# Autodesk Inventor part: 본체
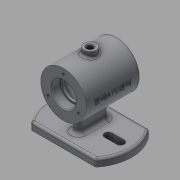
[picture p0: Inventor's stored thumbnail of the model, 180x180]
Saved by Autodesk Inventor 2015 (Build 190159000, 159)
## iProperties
Created: 2017-12
Part Number: 본체
Material: 일반
Document SubType Name: Modeling
Designer: SCD-A03
Density: 1 g/cm^3
Appearance: 기본값
Author: SCD-A03
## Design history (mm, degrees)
sketch "스케치1"
  geometry: L1 (-55, 0)-(55, 0); L2 (-42.426, 35)-(42.426, 35); L3 (-42.426, -35)-(42.426, -35); A1 r 55 centre (0, 0) between (-42.426, 35) and (-42.426, -35); A2 r 55 centre (0, 0) between (42.426, -35) and (42.426, 35); 1 further point
  constraints: 6 end point, 6 point on circle, 2 centre point, 2 parallel, 1 coincident, 1 horizontal
  dimensions: "d1" = 35 distance between parallel lines of L3 L1; "d2" = 35 distance between parallel lines of L2 L1
extrude "돌출1" new body sketch "스케치1" distance "d3" = 10; taper "d4" = 0 deg
sketch "스케치2"
  geometry: L1 (0, -15)-(0, 15); L2 (5, -15)-(5, 15); L3 (-5, 15)-(-5, -15); A1 r 55 centre (0, 0) between (42.426, -35) and (42.426, 35) reference; A2 r 5 centre (0, -15) between (-5, -15) and (5, -15); A3 r 5 centre (0, 15) between (5, 15) and (-5, 15)
  constraints: 8 end point, 4 point on circle, 4 tangent, 2 centre point, 1 midpoint, 1 parallel, 1 vertical
  dimensions: "d5" = 5 radius of A3; "d6" = 30 distance of L1.start L1.end
sketch "스케치6"
  geometry: C1 r 30 at (0, 62); 1 further point
  constraints: 1 centre point, 1 vertical alignment
  dimensions: "d18" = 60 diameter of C1; "d19" = 62 distance of point (0, 0) C1.centre
extrude "돌출5" join sketch "스케치6" stored distance "d20" = 70; taper "d21" = 0 deg
extrude "돌출6" join sketch "스케치2" stored distance "d22" = 70; taper "d23" = 0 deg
sketch "스케치7"
  geometry: L1 (-40, 0)-(-24, 0); L2 (-40, 5)-(-24, 5); L3 (-24, -5)-(-40, -5); A1 r 55 centre (0, 0) between (-42.426, 35) and (-42.426, -35) reference; A2 r 5 centre (-40, 0) between (-40, 5) and (-40, -5); A3 r 5 centre (-24, 0) between (-24, -5) and (-24, 5); 1 further point
  constraints: 8 end point, 4 point on circle, 4 tangent, 2 centre point, 1 horizontal, 1 horizontal alignment, 1 midpoint, 1 parallel
  dimensions: "d24" = 5 radius of A2; "d26" = 16 distance of L1.end L1.start; "d27" = 24 distance of A1.centre L1.end
extrude "돌출7" cut sketch "스케치7" distance "d28" = 70; taper "d29" = 0 deg
sketch "스케치8"
  geometry: L1 (35, 10)-(35, 0) reference; L2 (35, 0)-(-35, 0) reference; L3 (-35, 0)-(-35, 10) reference; L4 (-35, 10)-(-20, 10) reference; L5 (-20, 10)-(-20, 32) reference; L6 (-20, 32)-(-35, 32) reference; L7 (-35, 32)-(-35, 92) reference; L8 (-35, 92)-(35, 92) reference; L9 (35, 92)-(35, 32) reference; L10 (35, 32)-(20, 32) reference; L11 (20, 32)-(20, 10) reference; L12 (20, 10)-(35, 10) reference; L13 (35, 62)-(-35, 62); L14 (-35, 62)-(-35, 78); L15 (-23, 77.7)-(-23, 76); L16 (-23, 76)-(-20, 76); L17 (-20, 76)-(-20, 84); L18 (-17, 87)-(17, 87); L19 (20, 84)-(20, 76); L20 (20, 76)-(23, 76); L21 (23, 76)-(23, 77.7); L22 (23.3, 78)-(35, 78); L23 (-23.3, 78)-(-35, 78); A1 r 3 centre (-17, 84) between (-17, 87) and (-20, 84); A2 r 3 centre (17, 84) between (20, 84) and (17, 87); A3 r 0.3 centre (-23.3, 77.7) between (-23, 77.7) and (-23.3, 78); A4 r 0.3 centre (23.3, 77.7) between (23.3, 78) and (23, 77.7); 5 further points
  constraints: 22 end point, 12 point on line, 8 point on circle, 8 tangent, 6 perpendicular, 4 centre point, 2 equal radius, 2 midpoint, 1 horizontal, 1 vertical
  dimensions: "d30" = 32 diameter of L23 L13; "d31" = 28 diameter of L16 L13; "d32" = 50 diameter of L18 L13; "d33" = 32 diameter of L22 L13; "d34" = 12 distance of point (-23, 78) L14.end; "d35" = 40 distance of point (-20, 87) point (20, 87); "d36" = 3 distance of L15.end L16.end; "d37" = 12 distance of point (23, 78) L22.end; "d38" = 70 distance of L14.end L22.end (derived); "d66" = 3 radius of A1; "d67" = 0.3 radius of A3
revolve "회전1" sketch "스케치8" stored, may be unused: angle "d39" = 90 deg
node "작업 평면1"
sketch "스케치9"
  geometry: L1 (-30, -35)-(30, -35) reference; C1 r 8 at (0, 0); 1 further point
  constraints: 1 centre point, 1 coincident
  dimensions: "d41" = 16 diameter of C1
extrude "돌출8" join sketch "스케치9" stored distance "d42" = 70; taper "d43" = 0 deg
sketch "스케치10"
  geometry: C1 r 8 at (0, 0) reference
hole "구멍1" sketch "스케치10" at (0, 0) diameter "d44" = 8; stored, may be unused: countersink angle "d48" = 90 deg, drill point angle "d50" = 118 deg; dims "d45" = 6, "d46" = 4, "d47" = 2, "d49" = 30
sketch "스케치11"
  geometry: C1 r 16 at (0, 0) reference; 2 further points
  constraints: 1 vertical alignment
  dimensions: "d51" = 23 distance of C1.centre point (0, 23)
hole "구멍2" sketch "스케치11" at (0, 23) diameter "d52" = 3.242; stored, may be unused: countersink angle "d56" = 90 deg, drill point angle "d58" = 118 deg; dims "d53" = 8, "d54" = 4, "d55" = 2, "d57" = 10
fillet "모깎기1" dims "d62" = 5
fillet "모깎기2" dims "d63" = 3
fillet "모깎기3" dims "d64" = 3
fillet "모깎기4" dims "d65" = 3
chamfer "모따기1" distance "d68" = 1; stored, may be unused: second distance "d69" = 2, angle "d70" = 45 deg
node "작업 평면2"
sketch "스케치12"
  geometry: L1 (-35, 92)-(-35, 32) reference; 2 further points
  constraints: 1 other
  dimensions: "d72" = 35 distance from line of point (0, 62) L1; "d73" = 30 vertical distance of L1.start point (0, 62)
feature "엠보싱1" sketch "스케치12" dims "d74" = 0.5, "d75" = 0
chamfer "모따기2" distance "d76" = 1; stored, may be unused: second distance "d77" = 2, angle "d78" = 45 deg
node "솔리드1"
mirror "대칭1"
pattern_circular "원형 패턴1" dims angle "d60" = 360 deg
mirror "대칭2"
node "절단 모서리 투영1"
other parameters: "d40" = -99
